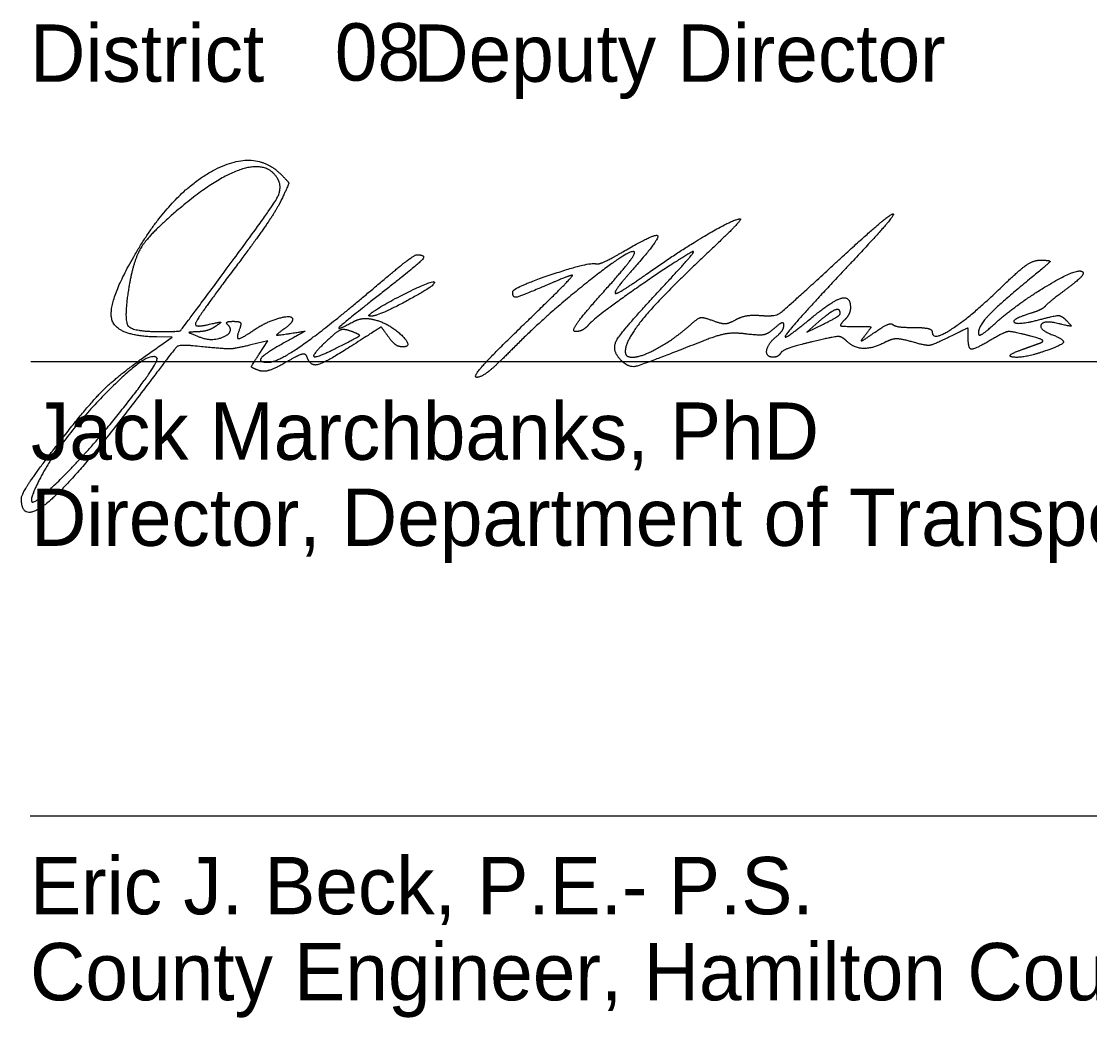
# Model space of a CAD drawing. Extents: x 0 to 69.5, y -4.5 to 22.
# Drawn here: x 26.197 to 28.806, y 6.217 to 8.649 of the extents above; entities that cross this region are included whole.
import ezdxf

# ---------------------------------------------------------------- set-up
doc = ezdxf.new("R2010")
doc.units = 0
for name, color, linetype in [('SC_Scratch1', 7, 'Continuous'), ('SH_Data', 7, 'Continuous'), ('SH_Text', 7, 'Continuous')]:
    doc.layers.add(name, color=color, linetype=linetype)

msp = doc.modelspace()

# ---------------------------------------------------------------- linework, layer by layer
at = {"layer": 'SC_Scratch1'}
msp.add_line((26.2182, 6.7095), (29.7182, 6.7095), dxfattribs=at)
at = {"layer": 'SH_Data'}
msp.add_line((26.2205, 7.8189), (29.7205, 7.8189), dxfattribs=at)
at = {"layer": 'SH_Text'}
for p, q in [((26.6827, 8.0239), (26.6827, 8.0239)), ((27.0481, 7.9341), (27.0481, 7.9341)), ((28.1971, 7.9361), (28.1971, 7.9361)), ((27.0033, 7.8924), (27.0033, 7.8924)), ((27.4199, 7.905), (27.4199, 7.905))]:
    msp.add_line(p, q, dxfattribs=at)
for points in [[(28.1453, 7.9164), (28.1158, 7.8908), (28.1564, 7.9104)], [(26.5351, 7.857), (26.5658, 7.8782), (26.528, 7.8788)], [(26.778, 7.8371), (26.7992, 7.8695), (26.7575, 7.8594)]]:
    msp.add_lwpolyline(points, dxfattribs=at)
for points in [[(26.4715, 8.0747), (26.5577, 8.225), (26.7658, 8.3411), (26.8315, 8.2754)], [(26.8225, 8.2662), (26.7966, 8.3082), (26.6705, 8.2671), (26.5751, 8.1855)], [(26.8315, 8.2754), (26.8503, 8.2566), (26.8503, 8.2516), (26.832, 8.2132)], [(26.6827, 8.0239), (26.8041, 8.1874), (26.8365, 8.2436), (26.8225, 8.2662)], [(26.832, 8.2132), (26.821, 8.1902), (26.7693, 8.1146), (26.717, 8.0453)], [(26.5751, 8.1855), (26.5085, 8.1284), (26.4696, 8.0643), (26.4585, 7.9931)], [(28.1795, 8.0536), (28.2544, 8.1227), (28.3205, 8.1793), (28.3262, 8.1793)], [(28.3262, 8.1793), (28.3319, 8.1794), (28.2799, 8.1193), (28.2106, 8.0457)], [(27.7252, 8.0331), (27.8057, 8.0898), (27.937, 8.167), (27.9527, 8.167)], [(27.9527, 8.167), (27.9576, 8.167), (27.9163, 8.1244), (27.8609, 8.0723)], [(27.6662, 8.0866), (27.745, 8.1328), (27.7572, 8.1196), (27.698, 8.0523)], [(26.528, 7.8788), (26.43, 7.8805), (26.4066, 7.9617), (26.4715, 8.0747)], [(27.0616, 8.0012), (27.112, 8.044), (27.1575, 8.0792), (27.1627, 8.0793)], [(27.1627, 8.0793), (27.1875, 8.0798), (27.1642, 8.0542), (27.0783, 7.987)], [(27.6943, 8.0864), (27.6847, 8.096), (27.4749, 7.9291), (27.3971, 7.8498)], [(27.8346, 8.086), (27.7855, 8.0582), (27.5972, 7.9259), (27.5839, 7.91)], [(27.6006, 8.0574), (27.6061, 8.0556), (27.6357, 8.0688), (27.6662, 8.0866)], [(27.6165, 7.986), (27.6628, 8.0378), (27.6978, 8.0829), (27.6943, 8.0864)], [(27.8609, 8.0723), (27.7613, 7.9786), (27.6721, 7.8704), (27.6721, 7.8434)], [(27.7694, 8.007), (27.8155, 8.0563), (27.8449, 8.0918), (27.8346, 8.086)], [(28.5877, 7.9973), (28.6329, 8.0411), (28.67, 8.0668), (28.6877, 8.0664)], [(28.6877, 8.0664), (28.712, 8.0659), (28.7082, 8.0596), (28.6596, 8.0196)], [(26.717, 8.0453), (26.6648, 7.9759), (26.6221, 7.9152), (26.6221, 7.9105)], [(27.3973, 7.9889), (27.3975, 7.9994), (27.5848, 8.0626), (27.6006, 8.0574)], [(27.698, 8.0523), (27.67, 8.0204), (27.6471, 7.9908), (27.6471, 7.9863)], [(28.0045, 7.9312), (28.0379, 7.9284), (28.0614, 7.9448), (28.1795, 8.0536)], [(28.2106, 8.0457), (28.0811, 7.9081), (28.049, 7.8609), (28.1311, 7.9286)], [(28.5689, 7.9061), (28.6225, 7.9549), (28.7695, 8.0449), (28.7864, 8.0393)], [(28.7864, 8.0393), (28.7948, 8.0365), (28.7795, 8.0178), (28.7524, 7.9976)], [(26.5366, 7.892), (26.5833, 7.892), (26.5879, 7.8961), (26.6827, 8.0239)], [(27.0481, 7.9341), (27.0685, 7.9519), (27.2005, 8.0177), (27.2057, 8.0125)], [(27.2057, 8.0125), (27.2119, 8.0064), (27.0692, 7.9295), (27.0516, 7.9295)], [(27.4199, 7.905), (27.4909, 7.9735), (27.5462, 8.0295), (27.5428, 8.0295)], [(27.5428, 8.0295), (27.5394, 8.0295), (27.5104, 8.0182), (27.4783, 8.0045)], [(27.6471, 7.9863), (27.6471, 7.9819), (27.6822, 8.0029), (27.7252, 8.0331)], [(28.6596, 8.0196), (28.5855, 7.9586), (28.5346, 7.9051), (28.5346, 7.8883)], [(26.4585, 7.9931), (26.4471, 7.9197), (26.4685, 7.892), (26.5366, 7.892)], [(26.8002, 7.817), (26.8233, 7.817), (26.9493, 7.9058), (27.0616, 8.0012)], [(27.0783, 7.987), (26.9851, 7.914), (26.9636, 7.8924), (27.0075, 7.9159)], [(27.4783, 8.0045), (27.4157, 7.9777), (27.3969, 7.974), (27.3973, 7.9889)], [(27.5506, 7.892), (27.5404, 7.892), (27.5692, 7.9333), (27.6165, 7.986)], [(27.6623, 7.8214), (27.6371, 7.8466), (27.666, 7.8967), (27.7694, 8.007)], [(28.4221, 7.8905), (28.4221, 7.8677), (28.5173, 7.9291), (28.5877, 7.9973)], [(28.7524, 7.9976), (28.7254, 7.9774), (28.7005, 7.9574), (28.6971, 7.9531)], [(28.1311, 7.9286), (28.1796, 7.9685), (28.2221, 7.9788), (28.2221, 7.9507)], [(27.0516, 7.9295), (27.0468, 7.9295), (27.0452, 7.9315), (27.0481, 7.9341)], [(28.1971, 7.9361), (28.1971, 7.9495), (28.173, 7.9404), (28.1453, 7.9164)], [(28.1564, 7.9104), (28.1788, 7.9213), (28.1971, 7.9328), (28.1971, 7.9361)], [(28.2221, 7.9507), (28.2221, 7.9418), (28.2153, 7.9277), (28.2071, 7.9195)], [(28.6627, 7.9366), (28.6131, 7.9211), (28.6326, 7.9075), (28.6845, 7.9213)], [(28.6971, 7.9531), (28.6936, 7.9489), (28.6781, 7.9414), (28.6627, 7.9366)], [(26.6221, 7.9105), (26.6221, 7.9057), (26.6375, 7.9054), (26.6564, 7.9098)], [(26.6325, 7.8787), (26.6624, 7.8667), (26.7186, 7.8913), (26.7011, 7.9087)], [(26.6564, 7.9098), (26.6819, 7.9157), (26.686, 7.9145), (26.6721, 7.9051)], [(26.7011, 7.9087), (26.6966, 7.9133), (26.7029, 7.917), (26.7151, 7.917)], [(26.7151, 7.917), (26.7296, 7.917), (26.7348, 7.9106), (26.73, 7.8982)], [(26.7661, 7.8964), (26.795, 7.9162), (26.8596, 7.9337), (26.8596, 7.9217)], [(26.8596, 7.9217), (26.8596, 7.9172), (26.8498, 7.9064), (26.8379, 7.8977)], [(27.0075, 7.9159), (27.0202, 7.9227), (27.0441, 7.9248), (27.0607, 7.9206)], [(27.0607, 7.9206), (27.0967, 7.9114), (27.1551, 7.8545), (27.1284, 7.8545)], [(27.5839, 7.91), (27.5757, 7.9001), (27.5607, 7.892), (27.5506, 7.892)], [(27.6901, 7.8295), (27.7118, 7.8295), (27.7932, 7.8747), (27.8295, 7.907)], [(27.8295, 7.907), (27.8498, 7.925), (27.8627, 7.9277), (27.8864, 7.9186)], [(27.8864, 7.9186), (27.9066, 7.911), (27.9254, 7.9117), (27.9415, 7.9207)], [(27.9415, 7.9207), (27.9548, 7.9283), (27.9832, 7.933), (28.0045, 7.9312)], [(28.0596, 7.908), (28.0596, 7.9151), (28.0494, 7.9117), (28.037, 7.9004)], [(28.0408, 7.8795), (28.0511, 7.8881), (28.0596, 7.9009), (28.0596, 7.908)], [(28.2071, 7.9195), (28.1954, 7.9078), (28.2013, 7.9045), (28.2336, 7.9045)], [(28.2797, 7.889), (28.3011, 7.904), (28.3218, 7.913), (28.3258, 7.9091)], [(28.3258, 7.9091), (28.3297, 7.9052), (28.3529, 7.902), (28.3775, 7.902)], [(28.6845, 7.9213), (28.7228, 7.9315), (28.7381, 7.9309), (28.7501, 7.9187)], [(28.7314, 7.9112), (28.6947, 7.9203), (28.6814, 7.8972), (28.7158, 7.884)], [(28.7501, 7.9187), (28.7628, 7.9058), (28.7592, 7.9044), (28.7314, 7.9112)], [(26.6283, 7.8914), (26.6059, 7.8905), (26.6063, 7.8892), (26.6325, 7.8787)], [(26.6721, 7.9051), (26.6617, 7.8981), (26.6421, 7.8919), (26.6283, 7.8914)], [(26.73, 7.8982), (26.7211, 7.875), (26.7339, 7.8743), (26.7661, 7.8964)], [(26.8379, 7.8977), (26.819, 7.8839), (26.821, 7.8826), (26.8535, 7.8875)], [(26.8535, 7.8875), (26.8903, 7.8931), (26.8902, 7.8928), (26.8447, 7.8677)], [(27.0033, 7.8924), (26.9861, 7.8987), (26.9696, 7.8936), (26.9502, 7.8759)], [(26.9752, 7.8561), (27.0215, 7.8798), (27.0251, 7.8844), (27.0033, 7.8924)], [(27.0937, 7.8792), (27.0768, 7.9032), (27.0748, 7.9028), (27.009, 7.8604)], [(27.3096, 7.7802), (27.2992, 7.7804), (27.3489, 7.8366), (27.4199, 7.905)], [(27.9675, 7.886), (27.9382, 7.8898), (27.8984, 7.8833), (27.8619, 7.8689)], [(28.037, 7.9004), (28.0213, 7.8863), (28.0001, 7.8819), (27.9675, 7.886)], [(28.2336, 7.9045), (28.2711, 7.9045), (28.2735, 7.9024), (28.258, 7.8831)], [(28.258, 7.8831), (28.2459, 7.8681), (28.2524, 7.8699), (28.2797, 7.889)], [(28.3775, 7.902), (28.402, 7.902), (28.4221, 7.8968), (28.4221, 7.8905)], [(28.5096, 7.8779), (28.5096, 7.9008), (28.5085, 7.9008), (28.4623, 7.878)], [(28.5346, 7.8883), (28.5346, 7.8809), (28.55, 7.8889), (28.5689, 7.9061)], [(28.6547, 7.8829), (28.6158, 7.8928), (28.5991, 7.8912), (28.5715, 7.8749)], [(28.6846, 7.8637), (28.696, 7.8679), (28.6842, 7.8754), (28.6547, 7.8829)], [(28.7158, 7.884), (28.7463, 7.8723), (28.7374, 7.8574), (28.6907, 7.842)], [(26.2842, 7.6148), (26.3618, 7.7152), (26.4419, 7.7925), (26.5351, 7.857)], [(26.6163, 7.8571), (26.5829, 7.8604), (26.5712, 7.8499), (26.4945, 7.7482)], [(26.7575, 7.8594), (26.7172, 7.8496), (26.6948, 7.8493), (26.6163, 7.8571)], [(26.8447, 7.8677), (26.7937, 7.8395), (26.7739, 7.817), (26.8002, 7.817)], [(27.009, 7.8604), (26.9402, 7.8161), (26.9027, 7.8063), (26.8946, 7.8307)], [(26.9502, 7.8759), (26.9059, 7.8354), (26.9172, 7.8265), (26.9752, 7.8561)], [(27.1284, 7.8545), (27.1188, 7.8545), (27.1032, 7.8656), (27.0937, 7.8792)], [(27.8619, 7.8689), (27.7159, 7.8112), (27.6808, 7.8029), (27.6623, 7.8214)], [(28.0338, 7.8295), (28.0154, 7.8295), (28.02, 7.8622), (28.0408, 7.8795)], [(28.1281, 7.867), (28.0898, 7.8577), (28.0555, 7.8456), (28.052, 7.8399)], [(28.2125, 7.8691), (28.2013, 7.8802), (28.1813, 7.8797), (28.1281, 7.867)], [(28.3088, 7.8666), (28.278, 7.8501), (28.2302, 7.8514), (28.2125, 7.8691)], [(28.3732, 7.8666), (28.3464, 7.8744), (28.3233, 7.8743), (28.3088, 7.8666)], [(28.4623, 7.878), (28.425, 7.8595), (28.4064, 7.8571), (28.3732, 7.8666)], [(28.5715, 7.8749), (28.5265, 7.8483), (28.5096, 7.8491), (28.5096, 7.8779)], [(28.6408, 7.848), (28.6546, 7.8529), (28.6742, 7.86), (28.6846, 7.8637)], [(26.528, 7.8277), (26.5071, 7.8486), (26.2886, 7.623), (26.2422, 7.5326)], [(26.7768, 7.7971), (26.7587, 7.804), (26.7588, 7.8077), (26.778, 7.8371)], [(26.8946, 7.8307), (26.8917, 7.8392), (26.8725, 7.834), (26.8434, 7.8169)], [(27.3971, 7.8498), (27.3592, 7.8113), (27.3199, 7.78), (27.3096, 7.7802)], [(27.6721, 7.8434), (27.6721, 7.8358), (27.6802, 7.8295), (27.6901, 7.8295)], [(28.052, 7.8399), (28.0485, 7.8342), (28.0403, 7.8295), (28.0338, 7.8295)], [(28.6907, 7.842), (28.6441, 7.8266), (28.5968, 7.8323), (28.6408, 7.848)], [(26.3123, 7.5514), (26.3799, 7.6204), (26.5357, 7.82), (26.528, 7.8277)], [(26.8434, 7.8169), (26.8178, 7.8018), (26.7878, 7.7929), (26.7768, 7.7971)], [(26.4945, 7.7482), (26.3422, 7.5462), (26.1971, 7.4175), (26.1971, 7.4845)], [(26.1971, 7.4845), (26.1971, 7.4942), (26.2363, 7.5528), (26.2842, 7.6148)], [(26.2422, 7.5326), (26.211, 7.4717), (26.2426, 7.4801), (26.3123, 7.5514)]]:
    msp.add_open_spline(points, degree=2, dxfattribs=at)

# ---------------------------------------------------------------- texts
at = {"layer": 'SC_Scratch1'}
for s, p in [('Eric J. Beck, P.E.- P.S.', (26.2182, 6.4695)), ('County Engineer, Hamilton County', (26.2182, 6.2595))]:
    msp.add_text(s, height=0.14, dxfattribs=at).set_placement(p)
at = {"layer": 'SH_Text'}
for s, p in [('District       Deputy Director', (26.2182, 8.5017)), ('              08', (26.2345, 8.5045)), ('Jack Marchbanks, PhD', (26.2205, 7.5789)), ('Director, Department of Transportation', (26.2205, 7.3689))]:
    msp.add_text(s, height=0.14, dxfattribs=at).set_placement(p)

doc.saveas('drawing.dxf')
